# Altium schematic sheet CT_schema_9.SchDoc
size 226 x 144 mm
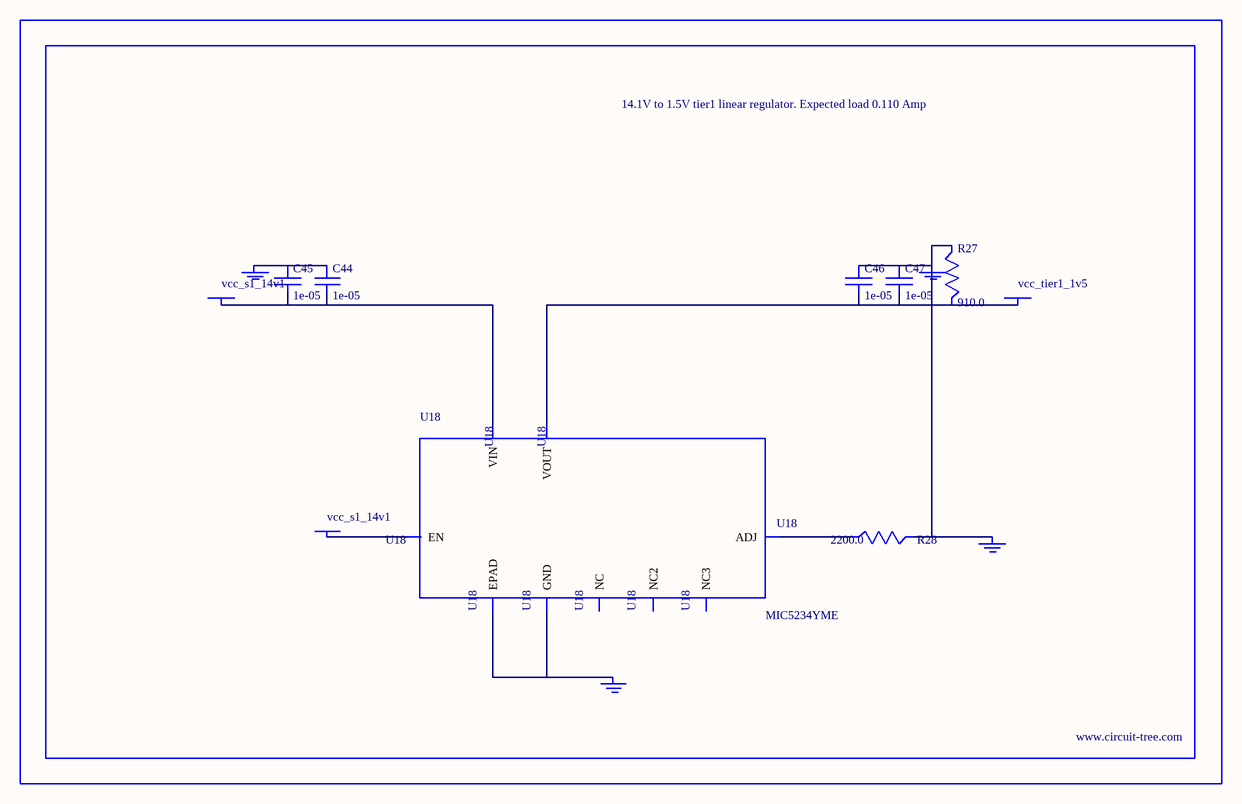
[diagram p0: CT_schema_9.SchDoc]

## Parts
BORDER8  (no value)
C44  1e-05  [C1210]
C45  1e-05  [C1210]
C46  1e-05  [C1210]
C47  1e-05  [C1210]
GND_INSTANCE_8_0  (no value)
GND_INSTANCE_8_1  (no value)
GND_INSTANCE_8_2  (no value)
GND_INSTANCE_8_3  (no value)
POWER_INSTANCE_8_0  vcc_tier1_1v5
POWER_INSTANCE_8_1  vcc_s1_14v1
POWER_INSTANCE_8_2  vcc_s1_14v1
R27  910.0  [R0603]
R28  2200.0  [R0603]
U18  MIC5234YME  [SOIC-8_EP]

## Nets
NetC44_1: C44.1 C45.1 GND_INSTANCE_8_3.0(GND)
NetC44_2: C44.2 C45.2 POWER_INSTANCE_8_2.0(PWR) U18.8(VIN)
NetC46_1: C46.1 C47.1 GND_INSTANCE_8_0.0(GND) GND_INSTANCE_8_1.0(GND) R27.1 R28.2
NetC46_2: C46.2 C47.2 POWER_INSTANCE_8_0.0(PWR) R27.2 U18.1(VOUT)
NetGND_INSTANCE_8_2_0: GND_INSTANCE_8_2.0(GND) U18.7(GND) U18.EPAD
NetPOWER_INSTANCE_8_1_0: POWER_INSTANCE_8_1.0(PWR) U18.5(EN)
NetR28_1: R28.1 U18.4(ADJ)

Not connected (* = marked no-connect by the designer): U18 2(NC) 3(NC2) 6(NC3)

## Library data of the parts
BORDER8 = BORDER_PAGE8
C44-C47 = C1210C106K5PACTU
GND_INSTANCE_8_0-GND_INSTANCE_8_3 = GND
POWER_INSTANCE_8_0-POWER_INSTANCE_8_2 = PWR
R27 = RC0603JR-07910RL
R28 = RC0603JR-072K2L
